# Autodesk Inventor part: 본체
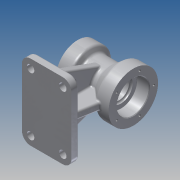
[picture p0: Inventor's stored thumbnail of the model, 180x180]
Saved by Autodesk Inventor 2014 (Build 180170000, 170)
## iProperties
Created: 2015-08
Part Number: 본체
Material: 알루미늄 6061
Document SubType Name: Modeling
Designer: SDA20
Density: 2.71 g/cm^3
Appearance: 알루미늄 - 평지
Mass: 1061.81 g
Surface Area: 751.05 cm^2
Volume: 391.813 cm^3
Author: SDA20
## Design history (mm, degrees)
sketch "스케치1"
  geometry: L1 (-574.06, -1.519)-(-484.06, -1.519); L2 (-574.06, -1.519)-(-574.06, 33.481); L3 (-574.06, 33.481)-(-554.06, 33.481); L4 (-554.06, 33.481)-(-548.864, 24.481); L5 (-548.864, 24.481)-(-520.745, 24.481); L6 (-520.745, 24.481)-(-504.06, 38.481); L7 (-504.06, 38.481)-(-484.06, 38.481); L8 (-484.06, 38.481)-(-484.06, -1.519)
  constraints: 16 end point, 3 parallel, 2 perpendicular, 1 horizontal
  dimensions: "d7" = 90 distance of L1.start L1.end; "d8" = 35 distance of L1.start L2.end; "d9" = 20 distance of L2.end L3.end; "d10" = 80 diameter of L7 L1; "d11" = 52 diameter of L5 L1; "d14" = 20 distance of L6.end L7.end
revolve "회전1" sketch "스케치1" stored, may be unused: angle "d17" = 90 deg
sketch "스케치2"
  geometry: C1 r 40 at (0, 0) reference; C2 r 26 at (0, 0)
  constraints: 1 centre point, 1 coincident
  dimensions: "d18" = 52 diameter of C2
extrude "돌출1" cut sketch "스케치2" distance "d19" = 20; taper "d20" = 0 deg
sketch "스케치3"
  geometry: C1 r 26 at (0, 0) reference; C2 r 19 at (0, 0)
  constraints: 1 centre point, 1 coincident
  dimensions: "d21" = 38 diameter of C2
extrude "돌출2" cut sketch "스케치3" distance "d22" = 3; taper "d23" = 0 deg
sketch "스케치4"
  geometry: C1 r 35 at (0, 0) reference; C2 r 20 at (0, 0)
  constraints: 1 centre point, 1 coincident
  dimensions: "d24" = 40 diameter of C2
extrude "돌출3" cut sketch "스케치4" distance "d25" = 17; taper "d26" = 0 deg
sketch "스케치5"
  geometry: C1 r 20 at (0, 0) reference; C2 r 16 at (0, 0)
  constraints: 1 centre point, 1 coincident
  dimensions: "d27" = 32 diameter of C2
extrude "돌출4" cut sketch "스케치5" stored distance "d28" = 17; taper "d29" = 0 deg
chamfer "모따기1" distance "d30" = 1; stored, may be unused: second distance "d31" = 2, angle "d32" = 45 deg
fillet "모깎기1" dims "d33" = 0.3
fillet "모깎기3" dims "d35" = 5
fillet "모깎기4" dims "d36" = 5
sketch "스케치6"
  geometry: L1 (0, 0)-(0, 27); C1 r 21 at (0, 0) reference; C2 r 27 at (0, 0)
  constraints: 2 end point, 1 centre point, 1 coincident, 1 vertical
  dimensions: "d37" = 54 diameter of C2; "d38" = 27 distance of L1.start L1.end
hole "구멍1" sketch "스케치6" at (0, 27) diameter "d39" = 3.459; stored, may be unused: countersink angle "d43" = 90 deg, drill point angle "d45" = 118 deg; dims "d40" = 10, "d41" = 4, "d42" = 2, "d44" = 13
sketch "스케치7"
  geometry: L1 (0, 0)-(0, 33); C1 r 27 at (0, 0) reference; C2 r 33 at (0, 0)
  constraints: 2 end point, 1 centre point, 1 coincident, 1 vertical
  dimensions: "d49" = 66 diameter of C2; "d50" = 33 distance of L1.start L1.end
hole "구멍2" sketch "스케치7" at (0, 33) diameter "d51" = 3.459; stored, may be unused: countersink angle "d55" = 90 deg, drill point angle "d57" = 118 deg; dims "d52" = 10, "d53" = 4, "d54" = 2, "d56" = 13
node "작업 평면1"
node "스케치8"
sketch "스케치9"
  geometry: L1 (-574.06, -36.519)-(-574.06, 33.481) reference; L2 (-574.06, -91.519)-(-494.06, -91.519); L3 (-494.06, -91.519)-(-494.06, -79.519); L4 (-494.06, -79.519)-(-574.06, -79.519); L5 (-574.06, -79.519)-(-574.06, -91.519)
  constraints: 8 end point, 2 perpendicular
  dimensions: "d62" = 80 distance of L2.start L2.end; "d63" = 12 distance of L2.end L3.end; "d64" = 80 distance of L3.end L4.end
extrude "돌출5" join sketch "스케치9" stored distance "d65" = 122; taper "d66" = 0 deg
node "작업 평면2"
sketch "스케치10"
  geometry: L1 (122, 12)-(122, 0) reference; L2 (122, 0)-(0, 0) reference; L3 (0, 0)-(0, 12) reference; L4 (0, 12)-(122, 12) reference; L5 (0, 12)-(10, 12); L6 (10, 12)-(37.923, 88.718); L7 (112, 12)-(84.077, 88.718); L8 (10, 12)-(112, 12); L9 (84.077, 88.718)-(71.095, 70.606); L10 (71.095, 70.606)-(51.998, 70.606); L11 (51.998, 70.606)-(37.923, 88.718); C1 r 26 at (61, 90) reference; C2 r 16 at (61, 90) reference
  constraints: 14 end point, 1 point on line
  dimensions: "d67" = 10 distance of L3.end L5.end; "d69" = 70 deg angle of L4 L6
extrude "돌출6" join sketch "스케치10" stored distance "d70" = 12; taper "d71" = 0 deg
node "작업 평면3"
sketch "스케치13"
  geometry: L1 (504.06, 17.481)-(504.06, 24.181) reference; L2 (507.06, 17.481)-(504.06, 17.481) reference; L3 (507.06, 14.481)-(507.06, 17.481) reference; L4 (573.06, 18.481)-(557.36, 18.481) reference; L5 (574.06, 19.481)-(573.06, 18.481) reference; L6 (574.06, -22.519)-(574.06, -36.519) reference; L7 (574.06, -36.519)-(556.947, -36.519) reference; L8 (552.617, -34.019)-(550.307, -30.019) reference; L9 (545.977, -27.519)-(540.06, -27.519) reference; L10 (540.06, -27.519)-(540.06, -79.519) reference; L11 (540.06, -79.519)-(574.06, -79.519) reference; L12 (574.06, -79.519)-(574.06, -91.519) reference; L13 (574.06, -91.519)-(494.06, -91.519) reference; L14 (494.06, -91.519)-(494.06, -79.519) reference; L15 (494.06, -79.519)-(528.06, -79.519) reference; L16 (528.06, -79.519)-(528.06, -27.519) reference; L17 (528.06, -27.519)-(522.564, -27.519) reference; L18 (519.351, -28.689)-(505.454, -40.349) reference; L19 (502.24, -41.519)-(484.06, -41.519) reference; L20 (484.06, -41.519)-(484.06, -28.519) reference; L21 (485.06, 24.481)-(484.06, 25.481) reference; L22 (503.76, 24.481)-(485.06, 24.481) reference; L23 (485.06, -27.519)-(503.76, -27.519) reference; L24 (484.06, -28.519)-(485.06, -27.519) reference; L25 (484.06, 25.481)-(484.06, 29.751) reference; L26 (484.06, 29.751)-(497.06, 29.751) reference; L27 (497.06, 29.751)-(498.099, 31.481) reference; L28 (498.099, 31.481)-(497.06, 33.21) reference; L29 (497.06, 33.21)-(484.06, 33.21) reference; L30 (484.06, 33.21)-(484.06, 38.481) reference; L31 (484.06, 38.481)-(502.24, 38.481) reference; L32 (505.454, 37.311)-(519.351, 25.651) reference; L33 (522.564, 24.481)-(545.977, 24.481) reference; L34 (550.307, 26.981)-(552.617, 30.981) reference; L35 (556.947, 33.481)-(574.06, 33.481) reference; L36 (574.06, 33.481)-(574.06, 27.21) reference; L37 (574.06, 27.21)-(561.06, 27.21) reference; L38 (561.06, 27.21)-(560.021, 25.481) reference; L39 (560.021, 25.481)-(561.06, 23.751) reference; L40 (561.06, 23.751)-(574.06, 23.751) reference; L41 (574.06, 23.751)-(574.06, 19.481) reference; L42 (573.06, -21.519)-(574.06, -22.519) reference; L43 (557.36, -21.519)-(573.06, -21.519) reference; L44 (507.06, -20.519)-(507.06, -17.519) reference; L45 (504.06, -20.519)-(507.06, -20.519) reference; L46 (504.06, -27.219)-(504.06, -20.519) reference; L47 (504.06, -79.519)-(496.122, -34.498); L48 (564.06, -79.519)-(564.06, -29.746); L49 (564.06, -29.746)-(543.395, -23.24); L50 (543.395, -23.24)-(519.98, -23.24); L51 (519.98, -23.24)-(496.122, -34.498); L52 (504.06, -79.519)-(564.06, -79.519); L53 (564.06, -29.746)-(564.06, -79.519); L54 (534.062, -23.24)-(534.06, -79.519); L55 (557.06, 18.181)-(557.06, 14.481) reference; L56 (557.06, 14.481)-(507.06, 14.481) reference; L57 (507.06, -17.519)-(557.06, -17.519) reference; L58 (557.06, -17.519)-(557.06, -21.219) reference; A1 r 0.3 centre (503.76, 24.181) between (503.76, 24.481) and (504.06, 24.181) reference; A2 r 0.3 centre (557.36, 18.181) between (557.06, 18.181) and (557.36, 18.481) reference; A3 r 5 centre (556.947, -31.519) between (552.617, -34.019) and (556.947, -36.519) reference; A4 r 5 centre (545.977, -32.519) between (550.307, -30.019) and (545.977, -27.519) reference; A5 r 5 centre (522.564, -32.519) between (522.564, -27.519) and (519.351, -28.689) reference; A6 r 5 centre (502.24, -36.519) between (502.24, -41.519) and (505.454, -40.349) reference; A7 r 0.3 centre (503.76, -27.219) between (504.06, -27.219) and (503.76, -27.519) reference; A8 r 5 centre (502.24, 33.481) between (505.454, 37.311) and (502.24, 38.481) reference; A9 r 5 centre (522.564, 29.481) between (519.351, 25.651) and (522.564, 24.481) reference; A10 r 5 centre (545.977, 29.481) between (545.977, 24.481) and (550.307, 26.981) reference; A11 r 5 centre (556.947, 28.481) between (556.947, 33.481) and (552.617, 30.981) reference; A12 r 0.3 centre (557.36, -21.219) between (557.36, -21.519) and (557.06, -21.219) reference
  constraints: 16 end point, 3 perpendicular, 3 point on line, 1 collinear, 1 midpoint
  dimensions: "d78" = 10 distance of L14.end L47.start; "d80" = 10 distance of L11.end L48.start
  node "절단 모서리 투영4"
node "스케치14"
extrude "돌출7" join sketch "스케치13" stored distance "d81" = 12; taper "d82" = 0 deg
sketch "스케치15"
  geometry: L1 (504.06, 17.481)-(504.06, 24.181) reference; L2 (507.06, 17.481)-(504.06, 17.481) reference; L3 (507.06, 14.481)-(507.06, 17.481) reference; L4 (573.06, 18.481)-(557.36, 18.481) reference; L5 (574.06, 19.481)-(573.06, 18.481) reference; L6 (574.06, -22.519)-(574.06, -36.519) reference; L7 (574.06, -36.519)-(556.947, -36.519) reference; L8 (552.617, -34.019)-(550.307, -30.019) reference; L9 (545.977, -27.519)-(540.06, -27.519) reference; L10 (540.06, -27.519)-(540.06, -79.519) reference; L11 (540.06, -79.519)-(574.06, -79.519) reference; L12 (574.06, -79.519)-(574.06, -91.519) reference; L13 (574.06, -91.519)-(494.06, -91.519) reference; L14 (494.06, -91.519)-(494.06, -79.519) reference; L15 (494.06, -79.519)-(504.06, -79.519) reference; L16 (503.76, 24.481)-(485.06, 24.481) reference; L17 (485.06, 24.481)-(484.06, 25.481) reference; L18 (484.06, -41.519)-(484.06, -28.519) reference; L19 (497.36, -41.519)-(484.06, -41.519) reference; L20 (485.06, -27.519)-(503.76, -27.519) reference; L21 (484.06, -28.519)-(485.06, -27.519) reference; L22 (484.06, 25.481)-(484.06, 29.751) reference; L23 (484.06, 29.751)-(497.06, 29.751) reference; L24 (497.06, 29.751)-(498.099, 31.481) reference; L25 (498.099, 31.481)-(497.06, 33.21) reference; L26 (497.06, 33.21)-(484.06, 33.21) reference; L27 (484.06, 33.21)-(484.06, 38.481) reference; L28 (484.06, 38.481)-(502.24, 38.481) reference; L29 (505.454, 37.311)-(519.351, 25.651) reference; L30 (522.564, 24.481)-(545.977, 24.481) reference; L31 (550.307, 26.981)-(552.617, 30.981) reference; L32 (556.947, 33.481)-(574.06, 33.481) reference; L33 (574.06, 33.481)-(574.06, 27.21) reference; L34 (574.06, 27.21)-(561.06, 27.21) reference; L35 (561.06, 27.21)-(560.021, 25.481) reference; L36 (560.021, 25.481)-(561.06, 23.751) reference; L37 (561.06, 23.751)-(574.06, 23.751) reference; L38 (574.06, 23.751)-(574.06, 19.481) reference; L39 (573.06, -21.519)-(574.06, -22.519) reference; L40 (557.36, -21.519)-(573.06, -21.519) reference; L41 (507.06, -20.519)-(507.06, -17.519) reference; L42 (504.06, -20.519)-(507.06, -20.519) reference; L43 (504.06, -27.219)-(504.06, -20.519) reference; L44 (574.06, -79.519)-(564.06, -79.519); L45 (564.06, -79.519)-(564.06, -29.137); L46 (564.06, -29.137)-(533.949, -20.063); L47 (533.949, -20.063)-(533.949, -79.519); L48 (564.06, -79.519)-(533.949, -79.519); L49 (504.06, -79.519)-(497.36, -41.519) reference; L50 (557.06, 18.181)-(557.06, 14.481) reference; L51 (557.06, 14.481)-(507.06, 14.481) reference; L52 (507.06, -17.519)-(557.06, -17.519) reference; L53 (557.06, -17.519)-(557.06, -21.219) reference; A1 r 0.3 centre (503.76, 24.181) between (503.76, 24.481) and (504.06, 24.181) reference; A2 r 0.3 centre (557.36, 18.181) between (557.06, 18.181) and (557.36, 18.481) reference; A3 r 5 centre (556.947, -31.519) between (552.617, -34.019) and (556.947, -36.519) reference; A4 r 5 centre (545.977, -32.519) between (550.307, -30.019) and (545.977, -27.519) reference; A5 r 0.3 centre (503.76, -27.219) between (504.06, -27.219) and (503.76, -27.519) reference; A6 r 5 centre (502.24, 33.481) between (505.454, 37.311) and (502.24, 38.481) reference; A7 r 5 centre (522.564, 29.481) between (519.351, 25.651) and (522.564, 24.481) reference; A8 r 5 centre (545.977, 29.481) between (545.977, 24.481) and (550.307, 26.981) reference; A9 r 5 centre (556.947, 28.481) between (556.947, 33.481) and (552.617, 30.981) reference; A10 r 0.3 centre (557.36, -21.219) between (557.36, -21.519) and (557.06, -21.219) reference
  constraints: 10 end point, 3 perpendicular, 1 point on line
  dimensions: "d83" = 10 distance of L11.end L44.end
extrude "돌출8" join sketch "스케치15" stored distance "d84" = 12; taper "d85" = 0 deg
fillet "모깎기5" dims "d86" = 3
fillet "모깎기6" dims "d87" = 3
fillet "모깎기7" dims "d88" = 3
sketch "스케치16"
  geometry: L1 (-52, 15)-(-52, 65.607) reference; L2 (-70, 65.607)-(-70, 15) reference; L3 (-107.716, 15)-(-70, 15) reference; L4 (-119, 12)-(-113.245, 12) reference; L5 (-122, 0)-(-122, 9) reference; L6 (0, 0)-(-122, 0) reference; L7 (0, 9)-(0, 0) reference; L8 (-8.755, 12)-(-3, 12) reference; L9 (-52, 15)-(-14.284, 15) reference; L10 (-14.284, 15)-(-37.519, 78.836) reference; L11 (-84.481, 78.836)-(-107.716, 15) reference; L12 (-61, 0)-(-61, 90); L13 (-37, 0)-(-37, 90); L14 (-85, 0)-(-37, 0); L15 (-79, 30)-(-79, 36); L16 (-91, 30)-(-91, 36); L17 (-43, 30)-(-43, 36); L18 (-31, 30)-(-31, 36); C1 r 16 at (-61, 90) reference; A1 r 26 centre (-61, 90) between (-52, 65.607) and (-37.519, 78.836) reference; A2 r 26 centre (-61, 90) between (-37.519, 78.836) and (-84.481, 78.836) reference; A3 r 26 centre (-61, 90) between (-84.481, 78.836) and (-70, 65.607) reference; A4 r 3 centre (-119, 9) between (-119, 12) and (-122, 9) reference; A5 r 3 centre (-3, 9) between (0, 9) and (-3, 12) reference; A6 r 6 centre (-85, 30) between (-91, 30) and (-79, 30); A7 r 6 centre (-85, 36) between (-79, 36) and (-91, 36); A8 r 6 centre (-37, 36) between (-31, 36) and (-43, 36); A9 r 6 centre (-37, 30) between (-43, 30) and (-31, 30)
  constraints: 14 end point, 8 point on circle, 6 symmetric about line, 4 centre point, 1 collinear, 1 midpoint, 1 parallel, 1 perpendicular, 4 other
  dimensions: "d90" = 24 distance between parallel lines of L13 L12; "d92" = 12 diameter of A6
extrude "돌출9" cut sketch "스케치16" distance "d98" = 30; taper "d99" = 0 deg
fillet "모깎기8" dims "d100" = 14
sketch "스케치17"
  geometry: C1 r 6 at (52, -11); C2 r 6 at (52, -105); C3 r 6 at (0, -11); C4 r 6 at (0, -105); A1 r 11 centre (52, -11) between (63, -11) and (52, 0) reference; A2 r 11 centre (0, -11) between (0, 0) and (-11, -11) reference; A3 r 11 centre (0, -105) between (-11, -105) and (0, -116) reference; A4 r 11 centre (52, -105) between (52, -116) and (63, -105) reference
  constraints: 4 centre point, 4 coincident
  dimensions: "d101" = 12 diameter of C1; "d102" = 12 diameter of C2; "d103" = 12 diameter of C3; "d104" = 12 diameter of C4
extrude "돌출10" cut sketch "스케치17" stored distance "d105" = 30; taper "d106" = 0 deg
fillet "모깎기9" dims "d107" = 3
sketch "스케치18"
  geometry: L1 (-504.06, -19.547)-(-504.06, -26.509) reference; L2 (-507.06, -19.547)-(-504.06, -19.547) reference; L3 (-507.06, -16.352)-(-507.06, -19.547) reference; L4 (-573.06, -20.598)-(-557.36, -20.598) reference; L5 (-574.06, -36.001)-(-574.06, -21.644) reference; L6 (-574.06, 32.963)-(-556.947, 32.963) reference; L7 (-545.977, 23.779)-(-522.564, 23.779) reference; L8 (-502.24, 38.028)-(-484.06, 38.028) reference; L9 (-484.06, -27.844)-(-484.06, -41.067) reference; L10 (-503.76, -26.817)-(-485.06, -26.817) reference; L11 (-485.06, 23.779)-(-503.76, 23.779) reference; L12 (-484.06, 38.028)-(-484.06, 24.806) reference; L13 (-484.06, -41.067)-(-495.864, -41.067) reference; L14 (-501.301, -79.519)-(-497.06, -79.519) reference; L15 (-494.06, -82.519)-(-494.06, -91.519) reference; L16 (-494.06, -91.519)-(-574.06, -91.519) reference; L17 (-574.06, -91.519)-(-574.06, -82.519) reference; L18 (-571.06, -79.519)-(-566.256, -79.519) reference; L19 (-561.06, -38.438)-(-561.06, -76.519) reference; L20 (-556.947, -38.438)-(-561.06, -38.438) reference; L21 (-543.06, -29.087)-(-545.977, -29.087) reference; L22 (-543.06, -76.519)-(-543.06, -29.087) reference; L23 (-561.06, -76.519)-(-543.06, -76.519) reference; L24 (-504.06, 23.471)-(-504.06, 16.509) reference; L25 (-504.06, 16.509)-(-507.06, 16.509) reference; L26 (-507.06, 16.509)-(-507.06, 13.313) reference; L27 (-557.36, 17.56)-(-573.06, 17.56) reference; L28 (-574.06, 18.605)-(-574.06, 32.963) reference; L29 (-565.923, -36.001)-(-574.06, -36.001) reference; L30 (-500.767, -43.567)-(-502.24, -43.567) reference; L31 (-522.564, -29.087)-(-525.06, -29.087) reference; L32 (-525.06, -29.087)-(-525.06, -76.519) reference; L33 (-525.06, -76.519)-(-506.577, -76.519) reference; L34 (-506.577, -76.519)-(-500.767, -43.567) reference; L35 (-557.06, -20.283)-(-557.06, -16.352) reference; L36 (-557.06, -16.352)-(-507.06, -16.352) reference; L37 (-507.06, 13.313)-(-557.06, 13.313) reference; L38 (-557.06, 13.313)-(-557.06, 17.245) reference; A1 r 3 centre (-497.06, -82.519) between (-494.06, -82.519) and (-497.06, -79.519) reference; A2 r 3 centre (-571.06, -82.519) between (-571.06, -79.519) and (-574.06, -82.519) reference; 9 further points
  constraints: 25 other
feature "엠보싱1" sketch "스케치18" dims "d7" = 90, "d8" = 35, "d9" = 20, "d10" = 80, "d11" = 52, "d14" = 20, "d112" = 0.5, "d113" = 0
fillet "모깎기10" dims "d114" = 3
node "솔리드1"
pattern_circular "원형 패턴1" dims angle "d47" = 360 deg
pattern_circular "원형 패턴3" dims angle "d116" = 360 deg
node "절단 모서리 투영1"
node "절단 모서리 투영5"
node "절단 모서리 투영6"
node "절단 모서리 투영7"
other parameters: "d95" = 12, "d96" = 6, "d97" = 6
